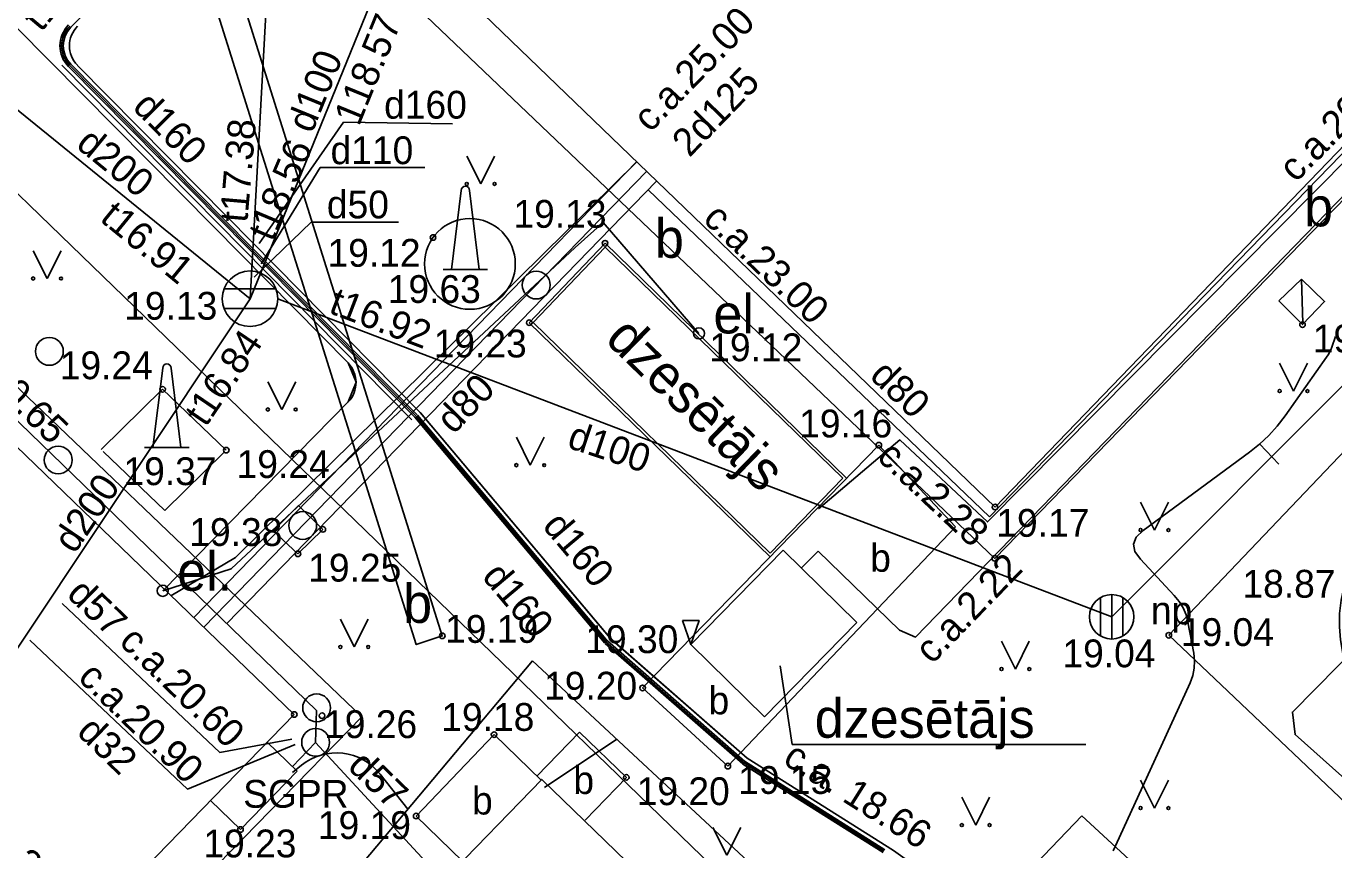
# Model space of a CAD drawing. Extents: x 532933 to 533143, y 328014 to 328163.
# Drawn here: x 533002.21 to 533025.73, y 328051.75 to 328066.56 of the extents above; entities that cross this region are included whole.
import ezdxf

# ---------------------------------------------------------------- set-up
doc = ezdxf.new("R2010")
doc.units = 0
for name, color, linetype in [('BUVE_BDET_####_####_#', 7, 'Continuous'), ('BUVE_BDET_####_TKST_#', 7, 'Continuous'), ('BUVE_EKAS_####_####_#', 7, 'Continuous'), ('BUVE_EKAS_BPAL_####_#', 7, 'Continuous'), ('BUVE_EKAS_RAKS_TKST_#', 7, 'Continuous'), ('BUVE_ELEM_####_####_#', 7, 'Continuous'), ('CELI_CMAL_####_####_#', 7, 'Continuous'), ('CELI_CSEG_####_TKST_#', 7, 'Continuous'), ('CKOM_ZEMJ_####_####_#', 7, 'Continuous'), ('ELEK_ACRL_####_####_#', 7, 'Continuous'), ('ELEK_ACRL_####_TKST_#', 7, 'Continuous'), ('ELEK_ELEM_####_####_#', 7, 'Continuous'), ('ELEK_VADP_VSPR_####_#', 7, 'Continuous'), ('ELEK_VADP_ZSPR_####_#', 7, 'Continuous'), ('GAZE_ELEM_####_TKST_#', 7, 'Continuous'), ('GAZE_SKAP_####_####_#', 7, 'Continuous'), ('GAZE_VADV_ASP1_####_#', 7, 'Continuous'), ('GAZE_VADV_ASP1_TKST_#', 7, 'Continuous'), ('LKAN_ELEM_####_####_#', 7, 'Continuous'), ('LKAN_ELEM_PAST_TKST_#', 7, 'Continuous'), ('LKAN_VADP_PAST_####_#', 7, 'Continuous'), ('LKAN_VADP_PAST_TKST_#', 7, 'Continuous'), ('NORB_ZOGS_ZSTP_####_#', 7, 'Continuous'), ('RELJ_AATZ_####_TKST_#', 7, 'Continuous'), ('RELJ_ELEM_####_####_#', 7, 'Continuous'), ('RELJ_HORZ_PAMT_####_#', 7, 'Continuous'), ('RELJ_NOGA_####_####_#', 7, 'Continuous'), ('ROBZ_UZMR_####_####_#', 7, 'Continuous'), ('SAKT_VADV_PKAB_####_#', 7, 'Continuous'), ('SILT_VADP_UDEN_####_#', 7, 'Continuous'), ('SILT_VADV_UDEN_####_#', 7, 'Continuous'), ('SILT_VADV_UDEN_TKST_#', 7, 'Continuous'), ('TERT_ELEM_####_####_#', 7, 'Continuous')]:
    doc.layers.add(name, color=color, linetype=linetype)

msp = doc.modelspace()

# ---------------------------------------------------------------- linework, layer by layer
at = {"layer": 'BUVE_BDET_####_####_#'}
for p, q in [((533012.622, 328062.658), (533011.259, 328061.229)), ((533016.966, 328058.433), (533012.622, 328062.658)), ((533024.735, 328061.621), (533025.141, 328062.012)), ((533025.141, 328062.012), (533025.169, 328061.223)), ((533015.589, 328057.017), (533011.259, 328061.229)), ((533004.667, 328060.031), (533003.562, 328058.947)), ((533005.812, 328058.936), (533004.667, 328060.031)), ((533004.707, 328057.852), (533003.598, 328058.913)), ((533005.777, 328058.901), (533004.707, 328057.852)), ((533013.297, 328054.661), (533017.544, 328059.027)), ((533017.544, 328059.027), (533018.921, 328057.559)), ((533007.099, 328057.073), (533007.549, 328057.512)), ((533018.921, 328057.559), (533014.83, 328053.255)), ((533014.83, 328053.255), (533013.297, 328054.661)), ((533010.627, 328053.821), (533009.227, 328052.357)), ((533011.471, 328053.002), (533010.627, 328053.821)), ((533011.396, 328053.075), (533012.163, 328053.867)), ((533010.062, 328051.548), (533009.227, 328052.357))]:
    msp.add_line(p, q, dxfattribs=at)
for points in [[(533025.141, 328062.012), (533025.559, 328061.613), (533025.162, 328061.194), (533024.735, 328061.621)], [(533007.099, 328057.073), (533006.655, 328057.485), (533007.112, 328057.941), (533007.549, 328057.512)], [(533012.262, 328052.281), (533013.005, 328053.053), (533012.163, 328053.867)]]:
    msp.add_lwpolyline(points, dxfattribs=at)
msp.add_circle((533010.193, 328062.286), 0.816, dxfattribs=at)
at = {"layer": 'BUVE_EKAS_####_####_#'}
for p, q in [((533019.634, 328057.914), (533031.702, 328070.431)), ((533009.143, 328068.025), (533019.634, 328057.914)), ((533007.034, 328054.184), (533000, 328060.965)), ((533000, 328046.956), (533007.034, 328054.184))]:
    msp.add_line(p, q, dxfattribs=at)
at = {"layer": 'BUVE_EKAS_BPAL_####_#'}
for p, q in [((533012.624, 328062.587), (533011.329, 328061.23)), ((533016.896, 328058.432), (533012.624, 328062.587)), ((533015.588, 328057.087), (533011.329, 328061.23)), ((533015.588, 328057.087), (533016.896, 328058.432)), ((533015.825, 328057.137), (533014.164, 328055.44)), ((533017.147, 328055.836), (533015.825, 328057.137)), ((533017.147, 328055.836), (533015.487, 328054.139)), ((533015.487, 328054.139), (533014.164, 328055.44))]:
    msp.add_line(p, q, dxfattribs=at)
msp.add_lwpolyline([(533009.717, 328051.192), (533011.485, 328053.017), (533020.228, 328044.544)], dxfattribs=at)
at = {"layer": 'BUVE_EKAS_RAKS_TKST_#'}
for p, q in [((533015.769, 328055.061), (533015.984, 328053.641)), ((533015.984, 328053.641), (533021.268, 328053.641))]:
    msp.add_line(p, q, dxfattribs=at)
at = {"layer": 'BUVE_ELEM_####_####_#'}
for p, q in [((533009.711, 328062.183), (533009.861, 328062.183)), ((533010.361, 328062.183), (533010.511, 328062.183)), ((533004.344, 328058.987), (533004.494, 328058.987)), ((533004.994, 328058.987), (533005.144, 328058.987))]:
    msp.add_line(p, q, dxfattribs=at)
for points in [[(533009.861, 328062.183), (533010.361, 328062.183), (533010.186, 328063.608)], [(533010.036, 328063.608), (533009.861, 328062.183)], [(533004.494, 328058.987), (533004.994, 328058.987), (533004.819, 328060.412)], [(533004.669, 328060.412), (533004.494, 328058.987)]]:
    msp.add_lwpolyline(points, dxfattribs=at)
for centre in [(533011.384, 328061.906), (533002.632, 328060.713), (533002.79, 328058.759), (533007.187, 328057.582), (533007.436, 328054.303), (533007.418, 328053.682)]:
    msp.add_circle(centre, 0.25, dxfattribs=at)
for centre in [(533010.111, 328063.608), (533004.744, 328060.412)]:
    msp.add_arc(centre, 0.075, 0, 180, dxfattribs=at)
at = {"layer": 'CELI_CMAL_####_####_#'}
for points in [[(533000, 328066.543), (533004.338, 328071.006), (533009.227, 328055.441), (533009.695, 328055.597), (533004.734, 328071.393), (533007.479, 328074.224), (533007.765, 328073.914), (533008.143, 328074.297)], [(533032.683, 328070.432), (533019.631, 328056.99), (533008.246, 328067.854)], [(533000, 328062.03), (533008.25, 328054.143)], [(533000, 328045.688), (533008.25, 328054.143)]]:
    msp.add_lwpolyline(points, dxfattribs=at)
at = {"layer": 'CKOM_ZEMJ_####_####_#'}
for p, q in [((533011.319, 328055.149), (533007.875, 328051.053)), ((533011.319, 328055.149), (533017.946, 328048.981)), ((533011.531, 328052.868), (533012.833, 328053.741)), ((533007.167, 328053.271), (533007.002, 328053.139)), ((533008.581, 328053.109), (533009.074, 328052.479)), ((533017.946, 328048.981), (533021.195, 328052.362)), ((533021.195, 328052.362), (533025.595, 328048.296))]:
    msp.add_line(p, q, dxfattribs=at)
msp.add_arc((533007.794, 328052.492), 1, 38.0762, 128.8238, dxfattribs=at)
at = {"layer": 'ELEK_ACRL_####_####_#'}
for p, q in [((533002.043, 328066.538), (533005.58, 328062.956)), ((533005.665, 328063.012), (533002.855, 328065.858)), ((533005.75, 328063.068), (533002.996, 328065.858)), ((533005.836, 328063.124), (533003.137, 328065.857)), ((533005.58, 328062.956), (533008.001, 328060.505)), ((533009.151, 328059.482), (533005.665, 328063.012)), ((533009.222, 328059.552), (533005.75, 328063.068)), ((533009.293, 328059.623), (533005.836, 328063.124)), ((533008.006, 328059.807), (533004.67, 328056.408)), ((533012.726, 328055.541), (533009.304, 328059.611)), ((533012.649, 328055.477), (533009.228, 328059.547)), ((533015.122, 328053.31), (533012.639, 328055.488)), ((533015.176, 328053.396), (533012.705, 328055.563)), ((533017.637, 328051.726), (533015.11, 328053.32)), ((533017.808, 328051.736), (533015.176, 328053.396))]:
    msp.add_line(p, q, dxfattribs=at)
for centre, start, end in [((533003.352, 328066.209), 135.052, 224.6387), ((533007.645, 328060.153), 316.1914, 44.6387)]:
    msp.add_arc(centre, 0.5, start, end, dxfattribs=at)
at = {"layer": 'ELEK_ACRL_####_TKST_#'}
for p, q in [((533006.406, 328062.656), (533007.917, 328064.834)), ((533007.917, 328064.834), (533009.878, 328064.807)), ((533007.503, 328064.022), (533006.437, 328062.285)), ((533007.503, 328064.022), (533009.381, 328064.022)), ((533007.341, 328063.035), (533006.314, 328062.045)), ((533007.341, 328063.035), (533007.665, 328063.035)), ((533007.665, 328063.035), (533008.908, 328063.035))]:
    msp.add_line(p, q, dxfattribs=at)
at = {"layer": 'ELEK_ELEM_####_####_#'}
for centre in [(533014.31, 328061.036), (533004.67, 328056.408)]:
    msp.add_circle(centre, 0.1, dxfattribs=at)
at = {"layer": 'ELEK_VADP_VSPR_####_#'}
for points in [[(533005.836, 328063.124), (533003.137, 328065.857)], [(533020.447, 328049.851), (533017.808, 328051.736), (533015.176, 328053.396), (533012.716, 328055.553), (533009.299, 328059.617), (533005.836, 328063.124)]]:
    msp.add_lwpolyline(points, dxfattribs=at)
msp.add_arc((533003.493, 328066.209), 0.5, 135.052, 224.6387, dxfattribs=at)
at = {"layer": 'ELEK_VADP_ZSPR_####_#'}
for p, q in [((533002.043, 328066.538), (533005.58, 328062.956)), ((533002.975, 328065.837), (533005.725, 328063.052)), ((533003.017, 328065.879), (533005.776, 328063.085)), ((533005.58, 328062.956), (533008.001, 328060.505)), ((533005.725, 328063.052), (533009.204, 328059.529)), ((533005.776, 328063.085), (533009.246, 328059.571)), ((533009.202, 328059.53), (533012.621, 328055.464)), ((533009.248, 328059.569), (533012.667, 328055.502)), ((533012.625, 328055.46), (533015.097, 328053.293)), ((533012.664, 328055.505), (533015.136, 328053.338)), ((533015.1, 328053.29), (533017.621, 328051.701)), ((533015.132, 328053.341), (533017.653, 328051.751))]:
    msp.add_line(p, q, dxfattribs=at)
for points in [[(533011.636, 328075.174), (533003.019, 328066.541)], [(533004.67, 328056.408), (533005.897, 328056.804), (533012.082, 328062.584), (533012.59, 328063.029), (533014.31, 328061.036)], [(533008.001, 328060.505), (533008.145, 328060.157), (533008.006, 328059.807), (533004.67, 328056.408)]]:
    msp.add_lwpolyline(points, dxfattribs=at)
for radius in [0.53, 0.47]:
    msp.add_arc((533003.352, 328066.209), radius, 135.052, 224.6387, dxfattribs=at)
at = {"layer": 'GAZE_SKAP_####_####_#'}
for p, q in [((533006.549, 328053.685), (533007.085, 328053.164)), ((533007.085, 328053.164), (533006.068, 328052.115)), ((533005.53, 328052.638), (533006.068, 328052.115))]:
    msp.add_line(p, q, dxfattribs=at)
at = {"layer": 'GAZE_VADV_ASP1_####_#'}
for p, q in [((533019.535, 328057.737), (533031.217, 328069.776)), ((533013.549, 328063.777), (533005.821, 328055.817)), ((533013.396, 328063.62), (533019.535, 328057.737)), ((533007.435, 328054.257), (533007.418, 328053.682)), ((533007.418, 328053.682), (533007, 328053.246)), ((533007.418, 328053.682), (533009.717, 328051.192))]:
    msp.add_line(p, q, dxfattribs=at)
msp.add_lwpolyline([(533000, 328061.446), (533007.435, 328054.257)], dxfattribs=at)
at = {"layer": 'GAZE_VADV_ASP1_TKST_#'}
for points in [[(533002.862, 328056.177), (533005.697, 328053.502), (533006.988, 328053.739)], [(533002.281, 328055.518), (533005.115, 328052.843), (533007.051, 328053.645)]]:
    msp.add_lwpolyline(points, dxfattribs=at)
at = {"layer": 'LKAN_ELEM_####_####_#'}
for p, q in [((533005.771, 328061.835), (533006.707, 328061.835)), ((533005.771, 328061.485), (533006.707, 328061.485)), ((533021.731, 328055.54), (533021.731, 328056.34)), ((533021.531, 328055.593), (533021.531, 328056.286)), ((533021.931, 328055.593), (533021.931, 328056.286))]:
    msp.add_line(p, q, dxfattribs=at)
for centre, radius in [((533006.239, 328061.66), 0.5), ((533021.731, 328055.94), 0.4)]:
    msp.add_circle(centre, radius, dxfattribs=at)
at = {"layer": 'LKAN_VADP_PAST_####_#'}
for p, q in [((533021.731, 328055.94), (533035.456, 328069.684)), ((533008.501, 328067.203), (533006.239, 328061.66)), ((533001.076, 328065.848), (533006.239, 328061.66)), ((533006.239, 328061.66), (533000, 328052.292)), ((533006.239, 328061.66), (533006.239, 328061.66)), ((533006.739, 328061.66), (533021.731, 328055.94))]:
    msp.add_line(p, q, dxfattribs=at)
msp.add_lwpolyline([(533006.239, 328061.66), (533006.594, 328068.094), (533020.443, 328082.363)], dxfattribs=at)
at = {"layer": 'NORB_ZOGS_ZSTP_####_#'}
for points in [[(533031.702, 328070.431), (533034.369, 328067.798), (533022.758, 328055.608)], [(533022.758, 328055.608), (533027.126, 328051.46), (533028.41, 328049.723), (533029.317, 328047.793), (533029.7, 328045.675), (533029.57, 328043.502), (533028.882, 328041.473), (533027.723, 328039.535), (533016.43, 328028.544)]]:
    msp.add_lwpolyline(points, dxfattribs=at)
at = {"layer": 'RELJ_ELEM_####_####_#'}
msp.add_lwpolyline([(533014.015, 328055.873), (533014.314, 328055.873), (533014.165, 328055.44)], close=True, dxfattribs=at)
for centre in [(533009.53, 328062.761), (533012.622, 328062.658), (533011.259, 328061.229), (533025.162, 328061.194), (533004.667, 328060.031), (533005.812, 328058.936), (533017.544, 328059.027), (533019.634, 328057.914), (533007.549, 328057.512), (533007.1, 328057.073), (533019.631, 328056.99), (533009.695, 328055.597), (533022.758, 328055.608), (533013.297, 328054.661), (533007.034, 328054.184), (533007.534, 328054.161), (533010.627, 328053.821), (533014.83, 328053.255), (533013.005, 328053.053), (533009.227, 328052.357), (533006.068, 328052.115)]:
    msp.add_circle(centre, 0.05, dxfattribs=at)
at = {"layer": 'RELJ_HORZ_PAMT_####_#'}
msp.add_line((533024.737, 328058.683), (533024.394, 328059.047), dxfattribs=at)
msp.add_lwpolyline([(533025.755, 328060.983), (533025.687, 328060.789), (533025.668, 328060.741), (533025.646, 328060.695), (533025.621, 328060.65), (533025.593, 328060.607), (533024.85, 328059.552), (533024.709, 328059.369), (533024.555, 328059.199), (533024.388, 328059.042), (533024.208, 328058.898), (533022.294, 328057.49), (533022.172, 328057.371), (533022.124, 328057.245), (533022.149, 328057.113), (533022.246, 328056.974), (533022.857, 328056.324), (533022.945, 328056.217), (533023.015, 328056.101), (533023.067, 328055.976), (533023.102, 328055.842), (533023.207, 328055.288), (533023.222, 328055.151), (533023.216, 328055.016), (533023.19, 328054.884), (533023.142, 328054.755), (533021.866, 328051.966), (533021.76, 328051.733)], dxfattribs=at)
at = {"layer": 'RELJ_NOGA_####_####_#'}
msp.add_spline([(533036.778, 328051.985), (533034.856, 328064.958), (533028.737, 328060.034), (533025.855, 328056.237), (533030.353, 328047.862), (533030.341, 328043.495), (533028.835, 328039.173), (533026.009, 328035.465), (533024.217, 328033.207)], degree=3, dxfattribs=at)
at = {"layer": 'ROBZ_UZMR_####_####_#'}
for points in [[(532993.949, 328071.405), (532999.253, 328076.841), (533001.874, 328079.871), (533025.763, 328107.492), (533029.138, 328104.514), (533014.917, 328088.072), (533037.903, 328068.645), (533030.421, 328036.082)], [(532979.271, 328056.364), (532993.949, 328071.405), (533030.421, 328036.082), (533029.157, 328030.58), (533020.389, 328026.352), (532998.604, 328038.086)]]:
    msp.add_lwpolyline(points, close=True, dxfattribs=at)
at = {"layer": 'SAKT_VADV_PKAB_####_#'}
msp.add_lwpolyline([(533013.194, 328064.12), (533005.977, 328057.009), (533004.818, 328056.317)], dxfattribs=at)
at = {"layer": 'SILT_VADP_UDEN_####_#'}
msp.add_lwpolyline([(533000, 328133.784), (533016.764, 328118.182), (533028.476, 328106.559), (533028.508, 328106.039), (533014.85, 328091.596), (533014.892, 328091.077), (533032.527, 328075.724), (533032.689, 328075.239), (533035.542, 328065.283), (533035.311, 328064.711), (533024.98, 328054.226), (533025.028, 328053.821), (533027.938, 328051.227), (533030.653, 328048.689), (533030.642, 328048.162), (533019.754, 328035.526), (533019.215, 328035.483), (533005.473, 328047.022)], dxfattribs=at)
at = {"layer": 'SILT_VADV_UDEN_####_#'}
for p, q in [((533013.191, 328064.125), (533005.229, 328055.925)), ((533016.151, 328056.816), (533016.451, 328057.12))]:
    msp.add_line(p, q, dxfattribs=at)
for points in [[(533027.625, 328066.202), (533028.036, 328065.793), (533028.054, 328065.738), (533018.204, 328055.576), (533017.913, 328055.697), (533016.451, 328057.12)], [(533016.457, 328057.881), (533017.919, 328059.122), (533019.499, 328057.646), (533027.341, 328065.568), (533027.208, 328065.769)], [(533013.37, 328063.951), (533005.409, 328055.751)]]:
    msp.add_lwpolyline(points, dxfattribs=at)
at = {"layer": 'TERT_ELEM_####_####_#'}
for p, q in [((533010.136, 328064.224), (533010.386, 328063.724)), ((533010.386, 328063.724), (533010.636, 328064.224)), ((533002.341, 328062.524), (533002.591, 328062.024)), ((533002.591, 328062.024), (533002.841, 328062.524)), ((533024.75, 328060.5), (533025, 328060)), ((533025, 328060), (533025.25, 328060.5)), ((533006.56, 328060.168), (533006.81, 328059.668)), ((533006.81, 328059.668), (533007.06, 328060.168)), ((533011.028, 328059.168), (533011.278, 328058.668)), ((533011.278, 328058.668), (533011.528, 328059.168)), ((533022.25, 328058), (533022.5, 328057.5)), ((533022.5, 328057.5), (533022.75, 328058)), ((533007.863, 328055.897), (533008.113, 328055.397)), ((533008.113, 328055.397), (533008.363, 328055.897)), ((533019.75, 328055.5), (533020, 328055)), ((533020, 328055), (533020.25, 328055.5)), ((533022.25, 328053), (533022.5, 328052.5)), ((533022.5, 328052.5), (533022.75, 328053)), ((533019.036, 328052.695), (533019.286, 328052.195)), ((533019.286, 328052.195), (533019.536, 328052.695)), ((533014.561, 328052.153), (533014.811, 328051.653)), ((533014.811, 328051.653), (533015.061, 328052.153))]:
    msp.add_line(p, q, dxfattribs=at)
for centre, radius in [((533010.136, 328063.724), 0.028), ((533010.636, 328063.724), 0.0263), ((533002.341, 328062.024), 0.028), ((533002.841, 328062.024), 0.0263), ((533024.75, 328060), 0.028), ((533025.25, 328060), 0.0263), ((533006.56, 328059.668), 0.028), ((533007.06, 328059.668), 0.0263), ((533011.028, 328058.667), 0.028), ((533011.528, 328058.667), 0.0263), ((533022.25, 328057.5), 0.028), ((533022.75, 328057.5), 0.0263), ((533007.863, 328055.397), 0.028), ((533008.363, 328055.397), 0.0263), ((533019.75, 328055), 0.028), ((533020.25, 328055), 0.0263), ((533022.25, 328052.5), 0.028), ((533022.75, 328052.5), 0.0263), ((533019.036, 328052.194), 0.028), ((533019.536, 328052.194), 0.0263)]:
    msp.add_circle(centre, radius, dxfattribs=at)

# ---------------------------------------------------------------- texts
at = {"layer": 'BUVE_BDET_####_TKST_#'}
for p in [(533017.203, 328056.75), (533014.297, 328054.187), (533011.867, 328052.754), (533010.045, 328052.385)]:
    msp.add_text(' b', height=0.5, dxfattribs=at).set_placement(p)
at = {"layer": 'BUVE_EKAS_RAKS_TKST_#'}
msp.add_text('dzesētājs', height=0.7, rotation=315.79, dxfattribs=at).set_placement((533012.601, 328060.905))
msp.add_text('dzesētājs', height=0.7, dxfattribs=at).set_placement((533016.392, 328053.765))
at = {"layer": 'CELI_CSEG_####_TKST_#'}
for s, p in [('b', (533025.191, 328062.962)), ('b', (533013.518, 328062.396)), (' b', (533008.732, 328055.831))]:
    msp.add_text(s, height=0.7, dxfattribs=at).set_placement(p)
at = {"layer": 'ELEK_ACRL_####_TKST_#'}
for s, rotation, p in [('d160', 314.6397, (533004.108, 328065.087)), ('d160', 310.057, (533011.48, 328057.564)), ('d160', 310.057, (533010.393, 328056.655)), ('c.a. 18.66', 327.7582, (533015.796, 328053.312))]:
    msp.add_text(s, height=0.5, rotation=rotation, dxfattribs=at).set_placement(p)
for s, p in [('d160', (533008.65, 328064.899)), ('d110', (533007.687, 328064.08)), ('d50', (533007.621, 328063.105))]:
    msp.add_text(s, height=0.5, dxfattribs=at).set_placement(p)
at = {"layer": 'ELEK_ELEM_####_####_#'}
for p in [(533014.31, 328061.036), (533004.67, 328056.408)]:
    msp.add_text(' el.', height=0.7, dxfattribs=at).set_placement(p)
at = {"layer": 'GAZE_ELEM_####_TKST_#'}
msp.add_text('SGPR', height=0.5, dxfattribs=at).set_placement((533006.116, 328052.506))
at = {"layer": 'GAZE_VADV_ASP1_TKST_#'}
for s, rotation, p in [('c.a.23.00', 316.2197, (533014.361, 328063.068)), ('c.a.20.65', 315.9636, (533000.692, 328060.926)), ('d80', 316.0553, (533017.359, 328060.249)), ('d80', 45.8459, (533009.898, 328059.207)), ('d57', 315.8608, (533002.923, 328056.321)), ('c.a.20.60', 315.8608, (533003.864, 328055.466)), ('c.a.20.90', 315.8608, (533003.124, 328054.823)), ('d32', 315.8608, (533003.104, 328053.843)), ('d57', 315.8608, (533007.975, 328053.225))]:
    msp.add_text(s, height=0.5, rotation=rotation, dxfattribs=at).set_placement(p)
at = {"layer": 'LKAN_ELEM_PAST_TKST_#'}
for s, p in [(' 19.13', (533003.792, 328061.283)), ('np', (533022.436, 328055.806)), (' 19.04', (533020.659, 328055.032))]:
    msp.add_text(s, height=0.5, dxfattribs=at).set_placement(p)
at = {"layer": 'LKAN_VADP_PAST_TKST_#'}
for s, rotation, p in [('t17.22', 50.154, (533002.483, 328066.442)), ('118.57', 67.7996, (533008.197, 328064.747)), ('d100', 67.7996, (533007.353, 328064.617)), ('t17.38', 85.0757, (533006.19, 328063.02)), ('d200', 320.7161, (533003.089, 328064.396)), ('t18.56', 67.1229, (533006.647, 328062.672)), ('t16.91', 320.7161, (533003.518, 328063.072)), ('t16.92', 339.117, (533007.633, 328061.413)), ('t16.84', 55.7809, (533005.443, 328059.337)), ('d100', 341.6667, (533011.92, 328058.99)), ('d200', 55.7809, (533003.084, 328057.056))]:
    msp.add_text(s, height=0.5, rotation=rotation, dxfattribs=at).set_placement(p)
at = {"layer": 'RELJ_AATZ_####_TKST_#'}
for s, p in [(' 19.13', (533010.79, 328062.936)), (' 19.12', (533007.447, 328062.235)), (' 19.63', (533008.53, 328061.584)), (' 19.23', (533009.355, 328060.604)), (' 19.12', (533014.31, 328060.536)), (' 19.11', (533025.162, 328060.694)), (' 19.24', (533002.632, 328060.213)), (' 19.16', (533015.926, 328059.166)), (' 19.24', (533005.812, 328058.436)), (' 19.37', (533003.778, 328058.308)), (' 19.38', (533004.962, 328057.214)), (' 19.17', (533019.471, 328057.379)), (' 19.25', (533007.1, 328056.573)), (' 18.87', (533023.896, 328056.284)), (' 19.19', (533009.56, 328055.472)), (' 19.04', (533022.79, 328055.415)), (' 19.30', (533012.081, 328055.287)), (' 19.20', (533011.34, 328054.451)), (' 19.26', (533007.385, 328053.759)), (' 19.18', (533009.492, 328053.889)), (' 19.15', (533014.83, 328052.755)), (' 19.20', (533013.005, 328052.553)), (' 19.19', (533007.274, 328051.944)), (' 19.23', (533005.215, 328051.614))]:
    msp.add_text(s, height=0.5, dxfattribs=at).set_placement(p)
at = {"layer": 'SILT_VADV_UDEN_TKST_#'}
for s, rotation, p in [('c.a.25.00', 45.8321, (533013.434, 328064.634)), ('c.a.20.49', 45.2905, (533025.04, 328063.735)), ('2d125', 45.8321, (533014.139, 328064.189)), ('c.a.2.28', 316.9561, (533017.485, 328058.792)), ('c.a.2.22', 45.8949, (533018.502, 328055.071)), ('c.a.21.95', 315.8474, (533001.16, 328052.217))]:
    msp.add_text(s, height=0.5, rotation=rotation, dxfattribs=at).set_placement(p)

doc.saveas('drawing.dxf')
